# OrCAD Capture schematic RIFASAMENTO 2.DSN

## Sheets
1 PAGE2: size A
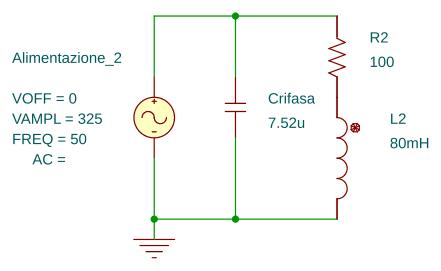
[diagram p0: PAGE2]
2 PAGE1: size A
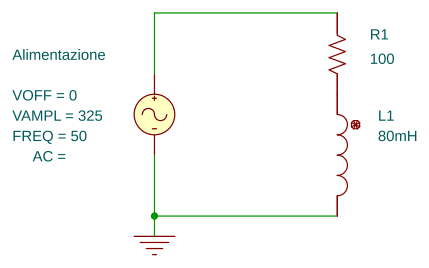
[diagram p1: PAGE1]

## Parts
sheet PAGE1
Alimentazione  VSIN
L1  80mH  [DISC/.350x.175/LS.200x.100/.034]
R1  100  [AX/RC05]
sheet PAGE2
Alimentazione_2  VSIN
Crifasa  7.52u  [RAD/CK05]
L2  80mH  [DISC/.350x.175/LS.200x.100/.034]
R2  100  [AX/RC05]

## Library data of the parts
Alimentazione Alimentazione_2 = VSIN: FREQ: 50; VAMPL: 325; VOFF: 0
L1 L2 = L
R1 R2 = R
Crifasa = C

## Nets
0: Alimentazione.2(-) Alimentazione_2.2(-) Crifasa.2 L1.2 L2.2
N00334: Alimentazione.1(+) R1.1
N00556: Alimentazione_2.1(+) Crifasa.1 R2.1
N01162: L1.1 R1.2
N01183: L2.1 R2.2
